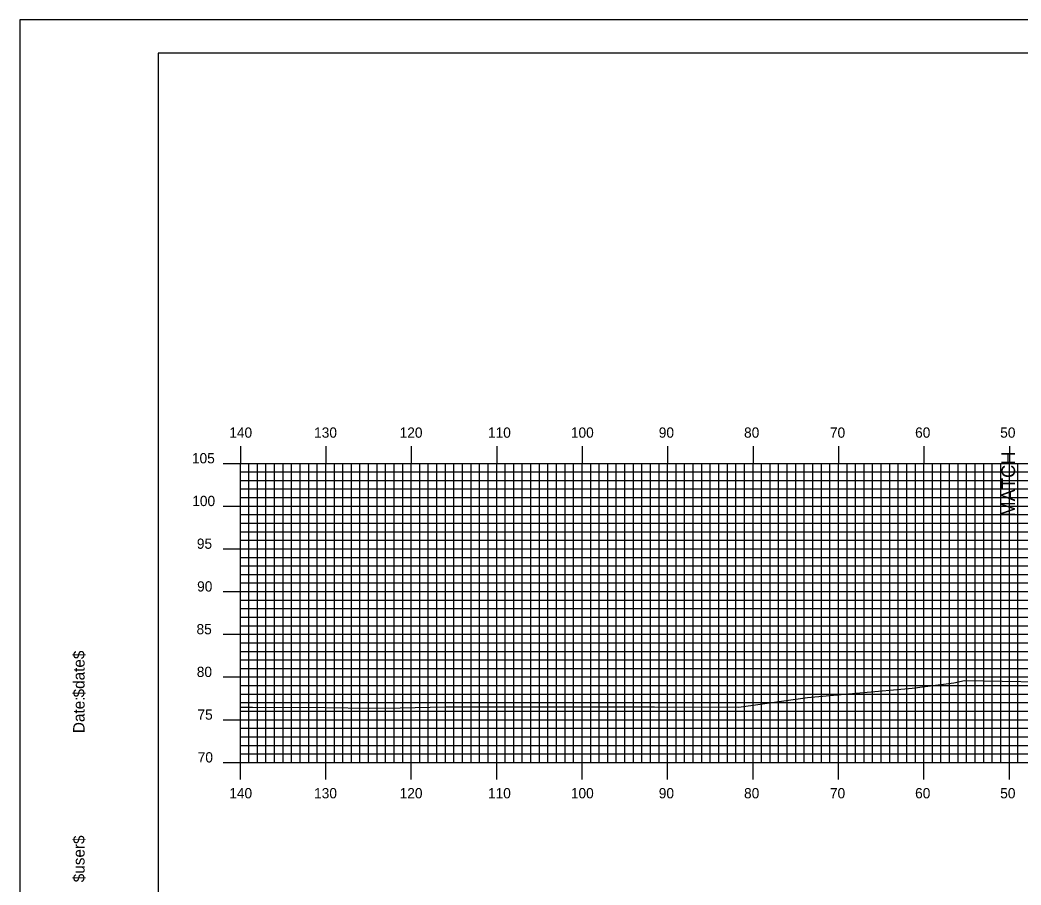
# Model space of a CAD drawing. Extents: x 1756282 to 1756625, y 442591 to 442811.
# Drawn here: x 1756281.8 to 1756398.9, y 442709.3 to 442810.5 of the extents above; entities that cross this region are included whole.
import ezdxf

# ---------------------------------------------------------------- set-up
doc = ezdxf.new("R2010")
doc.units = 0
for name, color, linetype in [('ANNOTATION', 7, 'Continuous'), ('BORDER', 7, 'Continuous'), ('H_V ANNOTATION', 7, 'Continuous'), ('MAJOR', 7, 'Continuous'), ('MINOR', 7, 'Continuous'), ('PLOT BOUNDARY', 7, 'Continuous'), ('S_Roadway_Centerline', 7, 'Continuous')]:
    doc.layers.add(name, color=color, linetype=linetype)

msp = doc.modelspace()

# ---------------------------------------------------------------- linework, layer by layer
at = {"layer": 'BORDER'}
msp.add_lwpolyline([(1756297.97, 442596.67), (1756617.97, 442596.67), (1756617.97, 442806.67), (1756297.97, 442806.67)], close=True, dxfattribs=at)
at = {"layer": 'MAJOR'}
for p, q in [((1756307.57, 442760.67), (1756307.57, 442758.67)), ((1756317.57, 442760.67), (1756317.57, 442758.67)), ((1756327.57, 442760.67), (1756327.57, 442758.67)), ((1756337.57, 442760.67), (1756337.57, 442758.67)), ((1756347.57, 442760.67), (1756347.57, 442758.67)), ((1756357.57, 442760.67), (1756357.57, 442758.67)), ((1756367.57, 442760.67), (1756367.57, 442758.67)), ((1756377.57, 442760.67), (1756377.57, 442758.67)), ((1756387.57, 442760.67), (1756387.57, 442758.67)), ((1756397.57, 442760.67), (1756397.57, 442758.67)), ((1756305.57, 442758.67), (1756307.57, 442758.67)), ((1756307.57, 442758.67), (1756587.57, 442758.67)), ((1756307.57, 442723.67), (1756307.57, 442758.67)), ((1756307.57, 442723.67), (1756307.57, 442758.67)), ((1756307.57, 442758.67), (1756587.57, 442758.67)), ((1756317.57, 442723.67), (1756317.57, 442758.67)), ((1756327.57, 442723.67), (1756327.57, 442758.67)), ((1756337.57, 442723.67), (1756337.57, 442758.67)), ((1756347.57, 442723.67), (1756347.57, 442758.67)), ((1756357.57, 442723.67), (1756357.57, 442758.67)), ((1756367.57, 442723.67), (1756367.57, 442758.67)), ((1756377.57, 442723.67), (1756377.57, 442758.67)), ((1756387.57, 442723.67), (1756387.57, 442758.67)), ((1756397.57, 442723.67), (1756397.57, 442758.67)), ((1756305.57, 442753.67), (1756307.57, 442753.67)), ((1756307.57, 442753.67), (1756587.57, 442753.67)), ((1756305.57, 442748.67), (1756307.57, 442748.67)), ((1756307.57, 442748.67), (1756587.57, 442748.67)), ((1756305.57, 442743.67), (1756307.57, 442743.67)), ((1756307.57, 442743.67), (1756587.57, 442743.67)), ((1756305.57, 442738.67), (1756307.57, 442738.67)), ((1756307.57, 442738.67), (1756587.57, 442738.67)), ((1756305.57, 442733.67), (1756307.57, 442733.67)), ((1756307.57, 442733.67), (1756587.57, 442733.67)), ((1756305.57, 442728.67), (1756307.57, 442728.67)), ((1756307.57, 442728.67), (1756587.57, 442728.67)), ((1756305.57, 442723.67), (1756307.57, 442723.67)), ((1756307.57, 442723.67), (1756587.57, 442723.67)), ((1756307.57, 442723.67), (1756587.57, 442723.67)), ((1756307.57, 442721.66), (1756307.57, 442723.67)), ((1756317.57, 442721.66), (1756317.57, 442723.67)), ((1756327.57, 442721.66), (1756327.57, 442723.67)), ((1756337.57, 442721.66), (1756337.57, 442723.67)), ((1756347.57, 442721.66), (1756347.57, 442723.67)), ((1756357.57, 442721.66), (1756357.57, 442723.67)), ((1756367.57, 442721.66), (1756367.57, 442723.67)), ((1756377.57, 442721.66), (1756377.57, 442723.67)), ((1756387.57, 442721.66), (1756387.57, 442723.67)), ((1756397.57, 442721.66), (1756397.57, 442723.67))]:
    msp.add_line(p, q, dxfattribs=at)
at = {"layer": 'MINOR'}
for p, q in [((1756307.57, 442757.67), (1756587.57, 442757.67)), ((1756307.57, 442757.67), (1756309.57, 442757.67)), ((1756308.57, 442723.67), (1756308.57, 442758.67)), ((1756309.57, 442723.67), (1756309.57, 442758.67)), ((1756310.57, 442723.67), (1756310.57, 442758.67)), ((1756311.57, 442723.67), (1756311.57, 442758.67)), ((1756312.57, 442723.67), (1756312.57, 442758.67)), ((1756313.57, 442723.67), (1756313.57, 442758.67)), ((1756314.57, 442723.67), (1756314.57, 442758.67)), ((1756315.57, 442723.67), (1756315.57, 442758.67)), ((1756316.57, 442723.67), (1756316.57, 442758.67)), ((1756318.57, 442723.67), (1756318.57, 442758.67)), ((1756319.57, 442723.67), (1756319.57, 442758.67)), ((1756320.57, 442723.67), (1756320.57, 442758.67)), ((1756321.57, 442723.67), (1756321.57, 442758.67)), ((1756322.57, 442723.67), (1756322.57, 442758.67)), ((1756323.57, 442723.67), (1756323.57, 442758.67)), ((1756324.57, 442723.67), (1756324.57, 442758.67)), ((1756325.57, 442723.67), (1756325.57, 442758.67)), ((1756326.57, 442723.67), (1756326.57, 442758.67)), ((1756328.57, 442723.67), (1756328.57, 442758.67)), ((1756329.57, 442723.67), (1756329.57, 442758.67)), ((1756330.57, 442723.67), (1756330.57, 442758.67)), ((1756331.57, 442723.67), (1756331.57, 442758.67)), ((1756332.57, 442723.67), (1756332.57, 442758.67)), ((1756333.57, 442723.67), (1756333.57, 442758.67)), ((1756334.57, 442723.67), (1756334.57, 442758.67)), ((1756335.57, 442723.67), (1756335.57, 442758.67)), ((1756336.57, 442723.67), (1756336.57, 442758.67)), ((1756338.57, 442723.67), (1756338.57, 442758.67)), ((1756339.57, 442723.67), (1756339.57, 442758.67)), ((1756340.57, 442723.67), (1756340.57, 442758.67)), ((1756341.57, 442723.67), (1756341.57, 442758.67)), ((1756342.57, 442723.67), (1756342.57, 442758.67)), ((1756343.57, 442723.67), (1756343.57, 442758.67)), ((1756344.57, 442723.67), (1756344.57, 442758.67)), ((1756345.57, 442723.67), (1756345.57, 442758.67)), ((1756346.57, 442723.67), (1756346.57, 442758.67)), ((1756348.57, 442723.67), (1756348.57, 442758.67)), ((1756349.57, 442723.67), (1756349.57, 442758.67)), ((1756350.57, 442723.67), (1756350.57, 442758.67)), ((1756351.57, 442723.67), (1756351.57, 442758.67)), ((1756352.57, 442723.67), (1756352.57, 442758.67)), ((1756353.57, 442723.67), (1756353.57, 442758.67)), ((1756354.57, 442723.67), (1756354.57, 442758.67)), ((1756355.57, 442723.67), (1756355.57, 442758.67)), ((1756356.57, 442723.67), (1756356.57, 442758.67)), ((1756358.57, 442723.67), (1756358.57, 442758.67)), ((1756359.57, 442723.67), (1756359.57, 442758.67)), ((1756360.57, 442723.67), (1756360.57, 442758.67)), ((1756361.57, 442723.67), (1756361.57, 442758.67)), ((1756362.57, 442723.67), (1756362.57, 442758.67)), ((1756363.57, 442723.67), (1756363.57, 442758.67)), ((1756364.57, 442723.67), (1756364.57, 442758.67)), ((1756365.57, 442723.67), (1756365.57, 442758.67)), ((1756366.57, 442723.67), (1756366.57, 442758.67)), ((1756368.57, 442723.67), (1756368.57, 442758.67)), ((1756369.57, 442723.67), (1756369.57, 442758.67)), ((1756370.57, 442723.67), (1756370.57, 442758.67)), ((1756371.57, 442723.67), (1756371.57, 442758.67)), ((1756372.57, 442723.67), (1756372.57, 442758.67)), ((1756373.57, 442723.67), (1756373.57, 442758.67)), ((1756374.57, 442723.67), (1756374.57, 442758.67)), ((1756375.57, 442723.67), (1756375.57, 442758.67)), ((1756376.57, 442723.67), (1756376.57, 442758.67)), ((1756378.57, 442723.67), (1756378.57, 442758.67)), ((1756379.57, 442723.67), (1756379.57, 442758.67)), ((1756380.57, 442723.67), (1756380.57, 442758.67)), ((1756381.57, 442723.67), (1756381.57, 442758.67)), ((1756382.57, 442723.67), (1756382.57, 442758.67)), ((1756383.57, 442723.67), (1756383.57, 442758.67)), ((1756384.57, 442723.67), (1756384.57, 442758.67)), ((1756385.57, 442723.67), (1756385.57, 442758.67)), ((1756386.57, 442723.67), (1756386.57, 442758.67)), ((1756388.57, 442723.67), (1756388.57, 442758.67)), ((1756389.57, 442723.67), (1756389.57, 442758.67)), ((1756390.57, 442723.67), (1756390.57, 442758.67)), ((1756391.57, 442723.67), (1756391.57, 442758.67)), ((1756392.57, 442723.67), (1756392.57, 442758.67)), ((1756393.57, 442723.67), (1756393.57, 442758.67)), ((1756394.57, 442723.67), (1756394.57, 442758.67)), ((1756395.57, 442723.67), (1756395.57, 442758.67)), ((1756396.57, 442723.67), (1756396.57, 442758.67)), ((1756398.57, 442723.67), (1756398.57, 442758.67)), ((1756307.57, 442756.67), (1756587.57, 442756.67)), ((1756307.57, 442756.67), (1756309.57, 442756.67)), ((1756307.57, 442755.67), (1756587.57, 442755.67)), ((1756307.57, 442755.67), (1756309.57, 442755.67)), ((1756307.57, 442754.67), (1756587.57, 442754.67)), ((1756307.57, 442754.67), (1756309.57, 442754.67)), ((1756307.57, 442752.67), (1756587.57, 442752.67)), ((1756307.57, 442752.67), (1756309.57, 442752.67)), ((1756307.57, 442751.67), (1756587.57, 442751.67)), ((1756307.57, 442751.67), (1756309.57, 442751.67)), ((1756307.57, 442750.67), (1756587.57, 442750.67)), ((1756307.57, 442750.67), (1756309.57, 442750.67)), ((1756307.57, 442749.67), (1756587.57, 442749.67)), ((1756307.57, 442749.67), (1756309.57, 442749.67)), ((1756307.57, 442747.67), (1756587.57, 442747.67)), ((1756307.57, 442747.67), (1756309.57, 442747.67)), ((1756307.57, 442746.67), (1756587.57, 442746.67)), ((1756307.57, 442746.67), (1756309.57, 442746.67)), ((1756307.57, 442745.67), (1756587.57, 442745.67)), ((1756307.57, 442745.67), (1756309.57, 442745.67)), ((1756307.57, 442744.67), (1756587.57, 442744.67)), ((1756307.57, 442744.67), (1756309.57, 442744.67)), ((1756307.57, 442742.67), (1756587.57, 442742.67)), ((1756307.57, 442742.67), (1756309.57, 442742.67)), ((1756307.57, 442741.67), (1756587.57, 442741.67)), ((1756307.57, 442741.67), (1756309.57, 442741.67)), ((1756307.57, 442740.67), (1756587.57, 442740.67)), ((1756307.57, 442740.67), (1756309.57, 442740.67)), ((1756307.57, 442739.67), (1756587.57, 442739.67)), ((1756307.57, 442739.67), (1756309.57, 442739.67)), ((1756307.57, 442737.67), (1756587.57, 442737.67)), ((1756307.57, 442737.67), (1756309.57, 442737.67)), ((1756307.57, 442736.67), (1756587.57, 442736.67)), ((1756307.57, 442736.67), (1756309.57, 442736.67)), ((1756307.57, 442735.67), (1756587.57, 442735.67)), ((1756307.57, 442735.67), (1756309.57, 442735.67)), ((1756307.57, 442734.67), (1756587.57, 442734.67)), ((1756307.57, 442734.67), (1756309.57, 442734.67)), ((1756307.57, 442732.67), (1756587.57, 442732.67)), ((1756307.57, 442732.67), (1756309.57, 442732.67)), ((1756307.57, 442731.67), (1756587.57, 442731.67)), ((1756307.57, 442731.67), (1756309.57, 442731.67)), ((1756307.57, 442730.67), (1756587.57, 442730.67)), ((1756307.57, 442730.67), (1756309.57, 442730.67)), ((1756307.57, 442729.67), (1756587.57, 442729.67)), ((1756307.57, 442729.67), (1756309.57, 442729.67)), ((1756307.57, 442727.67), (1756587.57, 442727.67)), ((1756307.57, 442727.67), (1756309.57, 442727.67)), ((1756307.57, 442726.67), (1756587.57, 442726.67)), ((1756307.57, 442726.67), (1756309.57, 442726.67)), ((1756307.57, 442725.67), (1756587.57, 442725.67)), ((1756307.57, 442725.67), (1756309.57, 442725.67)), ((1756307.57, 442724.67), (1756587.57, 442724.67)), ((1756307.57, 442724.67), (1756309.57, 442724.67))]:
    msp.add_line(p, q, dxfattribs=at)
at = {"layer": 'PLOT BOUNDARY'}
msp.add_lwpolyline([(1756281.78, 442590.55), (1756621.78, 442590.55), (1756621.78, 442810.55), (1756281.78, 442810.55)], close=True, dxfattribs=at)
at = {"layer": 'S_Roadway_Centerline'}
msp.add_lwpolyline([(1756307.57, 442730.14), (1756308.98, 442730.15), (1756317.6, 442730.09), (1756322.71, 442730.02), (1756326.26, 442730.07), (1756331.55, 442730.17), (1756338.58, 442730.18), (1756355.69, 442730.16), (1756356.04, 442730.18), (1756365.92, 442730.15), (1756373.94, 442731.27), (1756386.18, 442732.37), (1756391.07, 442732.99), (1756392.32, 442733.26), (1756405.53, 442733.01)], dxfattribs=at)

# ---------------------------------------------------------------- texts
at = {"layer": 'ANNOTATION'}
msp.add_text('MATCH', height=1.6, rotation=90, dxfattribs=at).set_placement((1756398.24, 442752.44))
at = {"layer": 'BORDER'}
for s, p in [('$date$', (1756289.34, 442731.28)), ('$date$', (1756289.34, 442731.28)), ('Date:', (1756289.34, 442727.1)), ('Date:', (1756289.34, 442727.1)), ('$user$', (1756289.34, 442709.65)), ('$user$', (1756289.34, 442709.65))]:
    msp.add_text(s, height=1.339, rotation=90, dxfattribs=at).set_placement(p)
at = {"layer": 'H_V ANNOTATION'}
for s, p in [('140', (1756306.27, 442761.67)), ('130', (1756316.2, 442761.67)), ('120', (1756326.21, 442761.67)), ('110', (1756336.55, 442761.67)), ('100', (1756346.25, 442761.67)), ('90', (1756356.54, 442761.67)), ('80', (1756366.52, 442761.67)), ('70', (1756376.57, 442761.67)), ('60', (1756386.54, 442761.67)), ('50', (1756396.5, 442761.67)), ('105', (1756301.9, 442758.67)), ('100', (1756301.94, 442753.67)), ('95', (1756302.48, 442748.67)), ('90', (1756302.51, 442743.67)), ('85', (1756302.44, 442738.67)), ('80', (1756302.47, 442733.67)), ('75', (1756302.55, 442728.67)), ('70', (1756302.58, 442723.67)), ('140', (1756306.27, 442719.47)), ('130', (1756316.2, 442719.47)), ('120', (1756326.21, 442719.47)), ('110', (1756336.55, 442719.47)), ('100', (1756346.25, 442719.47)), ('90', (1756356.54, 442719.47)), ('80', (1756366.52, 442719.47)), ('70', (1756376.57, 442719.47)), ('60', (1756386.54, 442719.47)), ('50', (1756396.5, 442719.47))]:
    msp.add_text(s, height=1.2, dxfattribs=at).set_placement(p)
at = {"layer": 'MAJOR'}
msp.add_text('-', height=0.012, dxfattribs=at).set_placement((1756307.56, 442723.67))

doc.saveas('drawing.dxf')
